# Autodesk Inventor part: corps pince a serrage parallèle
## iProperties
Created: 2011-09
Part Number: corps pince a serrage parallèle
Document SubType Name: Modeling
Designer: Dominique
Author: Dominique
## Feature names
1. Extrusion1
2. Extrusion2
3. Extrusion3
4. Perçage1 [Hole]
5. Perçage2 [Hole]
6. Perçage3 [Hole]
7. Perçage4 [Hole]
8. Extrusion4
9. Chanfrein1 [Chamfer]
10. Perçage5 [Hole]
11. Perçage6 [Hole]
12. Extrusion5
13. Extrusion6
14. Extrusion7
15. Perçage7 [Hole]
16. Extrusion8
